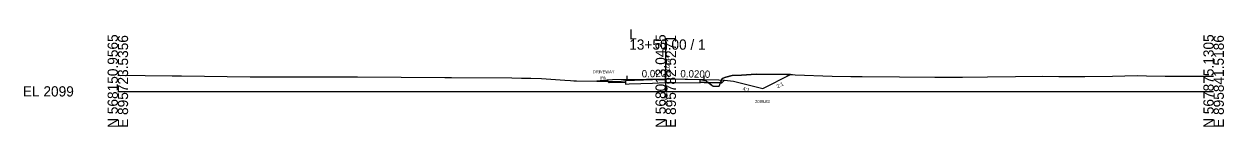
# Model space of a CAD drawing. Extents: x -26 to 1603, y -10 to 13527.
# Drawn here: x -25.7 to 302.8, y 990.3 to 1017 of the extents above; entities that cross this region are included whole.
import ezdxf

# ---------------------------------------------------------------- set-up
doc = ezdxf.new("R2010")
doc.units = 0
for name, color, linetype in [('Default', 7, 'Continuous'), ('Exist XS Center Line Elevation Label', 7, 'Continuous'), ('Exist XS Ground Line', 7, 'Continuous'), ('Old_Level_61', 7, 'Continuous'), ('Old_Level_63', 7, 'Continuous'), ('Prop XS Ditch Slope Text', 7, 'Continuous'), ('Prop XS Ditch Standard Text', 7, 'Continuous'), ('Prop XS Earthwork Shape', 7, 'Continuous'), ('Prop XS EOT Tick Mark', 7, 'Continuous'), ('Prop XS Finish Grade', 7, 'Continuous'), ('Prop XS Finish Grade Earthwork', 7, 'Continuous'), ('Prop XS Finish Grade Paved Shoulder', 7, 'Continuous'), ('Prop XS Finish Grade Pavement', 7, 'Continuous'), ('Prop XS Side Slope Text', 7, 'Continuous'), ('Prop XS Subgrade Earthwork', 7, 'Continuous'), ('Prop XSC Text', 7, 'Continuous')]:
    doc.layers.add(name, color=color, linetype=linetype)

msp = doc.modelspace()

# ---------------------------------------------------------------- linework, layer by layer
at = {"layer": 'Exist XS Ground Line'}
for p, q in [((0, 1004.41), (7.48, 1004.32)), ((7.48, 1004.32), (14.85, 1004.22)), ((14.85, 1004.22), (17.43, 1004.21)), ((17.43, 1004.21), (36.21, 1003.97)), ((36.21, 1003.97), (37.59, 1003.97)), ((37.59, 1003.97), (62.57, 1004)), ((62.57, 1004), (65.6, 1003.99)), ((65.6, 1003.99), (89.54, 1003.82)), ((89.54, 1003.82), (90.36, 1003.82)), ((90.36, 1003.82), (91.39, 1003.81)), ((91.39, 1003.81), (107.89, 1003.73)), ((107.89, 1003.73), (110.48, 1003.66)), ((110.48, 1003.66), (113.06, 1003.59)), ((113.06, 1003.59), (115.98, 1003.52)), ((115.98, 1003.52), (122.4, 1003.04)), ((122.4, 1003.04), (123.92, 1002.94)), ((123.92, 1002.94), (124.85, 1002.88)), ((124.85, 1002.88), (125.58, 1002.88)), ((125.58, 1002.88), (137.27, 1002.72)), ((137.27, 1002.72), (138.97, 1002.98)), ((138.97, 1002.98), (146.39, 1003.25)), ((146.39, 1003.25), (149.78, 1003.4)), ((149.78, 1003.4), (152.57, 1003.41)), ((152.57, 1003.41), (159.47, 1003.25)), ((159.47, 1003.25), (160.35, 1003.11)), ((160.35, 1003.11), (160.94, 1002.96)), ((160.94, 1002.96), (161.38, 1002.64)), ((161.38, 1002.64), (162.98, 1001.42)), ((164.61, 1001.42), (165.41, 1003.49)), ((165.41, 1003.49), (166.46, 1003.85)), ((166.46, 1003.85), (168.2, 1004.31)), ((168.2, 1004.31), (170.75, 1004.48)), ((170.75, 1004.48), (174.75, 1004.74)), ((174.75, 1004.74), (183.06, 1004.63)), ((183.06, 1004.63), (184.72, 1004.6)), ((184.72, 1004.6), (185.45, 1004.57)), ((185.45, 1004.57), (195.54, 1004.2)), ((195.54, 1004.2), (200.72, 1004.05)), ((200.72, 1004.05), (203.8, 1004.09)), ((203.8, 1004.09), (214.04, 1003.99)), ((214.04, 1003.99), (223.63, 1003.92)), ((223.63, 1003.92), (231.22, 1003.89)), ((231.22, 1003.89), (238.12, 1003.99)), ((238.12, 1003.99), (245.78, 1004.09)), ((245.78, 1004.09), (253.18, 1004.17)), ((253.18, 1004.17), (257.58, 1004.08)), ((257.58, 1004.08), (258.88, 1004.08)), ((258.88, 1004.08), (263.3, 1004.08)), ((263.3, 1004.08), (264.77, 1004.09)), ((264.77, 1004.09), (272.31, 1004.19)), ((272.31, 1004.19), (279.05, 1004.31)), ((279.05, 1004.31), (281.65, 1004.25)), ((281.65, 1004.25), (286.77, 1004.18)), ((286.77, 1004.18), (290.47, 1004.19)), ((290.47, 1004.19), (300, 1004.17)), ((162.98, 1001.42), (163.92, 1001.42)), ((163.92, 1001.42), (164.61, 1001.42))]:
    msp.add_line(p, q, dxfattribs=at)
at = {"layer": 'Old_Level_61'}
for p, q in [((138.96, 1002.98), (138.96, 1001.98)), ((139.96, 1002.02), (146.39, 1002.25)), ((146.39, 1002.25), (149.78, 1002.4)), ((149.78, 1002.4), (152.57, 1002.41)), ((152.57, 1002.41), (159.44, 1002.33)), ((159.44, 1002.33), (159.47, 1002.32)), ((159.47, 1002.32), (159.47, 1003.25)), ((138.96, 1001.98), (138.97, 1001.98)), ((138.97, 1001.98), (139.96, 1002.02))]:
    msp.add_line(p, q, dxfattribs=at)
at = {"layer": 'Old_Level_63'}
for p, q in [((150, 1000), (150, 1014.21)), ((0, 1000), (150, 1000)), ((150, 1000), (300, 1000))]:
    msp.add_line(p, q, dxfattribs=at)
at = {"layer": 'Prop XS Earthwork Shape'}
for points in [[(133.95, 1003.03), (131.14, 1002.8), (134.21, 1002.76)], [(133.95, 1003.03), (131.14, 1002.8), (134.21, 1002.76)], [(134.64, 1002.34), (134.21, 1002.76), (137.27, 1002.72), (138.96, 1002.98), (138.96, 1002.43)], [(134.64, 1002.34), (134.21, 1002.76), (137.27, 1002.72), (138.96, 1002.98), (138.96, 1002.43)], [(161.38, 1002.64), (161.67, 1002.41), (160.55, 1002.44), (159.47, 1002.46), (159.47, 1003.25), (160.35, 1003.11), (160.94, 1002.96)], [(161.38, 1002.64), (161.67, 1002.41), (160.55, 1002.44), (159.47, 1002.46), (159.47, 1003.25), (160.35, 1003.11), (160.94, 1002.96)], [(164.61, 1001.42), (164.97, 1002.35), (161.67, 1002.41), (162.98, 1001.42), (163.92, 1001.42)], [(164.61, 1001.42), (164.97, 1002.35), (161.67, 1002.41), (162.98, 1001.42), (163.92, 1001.42)], [(166.05, 1003.03), (168.56, 1002.83), (176.57, 1000.83), (184.14, 1004.61), (183.06, 1004.63), (174.75, 1004.74), (170.75, 1004.48), (168.2, 1004.31), (166.46, 1003.85), (165.41, 1003.49), (164.97, 1002.35), (165.36, 1002.34)], [(166.05, 1003.03), (168.56, 1002.83), (176.57, 1000.83), (184.14, 1004.61), (183.06, 1004.63), (174.75, 1004.74), (170.75, 1004.48), (168.2, 1004.31), (166.46, 1003.85), (165.41, 1003.49), (164.97, 1002.35), (165.36, 1002.34)]]:
    msp.add_lwpolyline(points, close=True, dxfattribs=at)
at = {"layer": 'Prop XS EOT Tick Mark'}
for p, q in [((139.45, 1003.23), (139.45, 1004.23)), ((160.55, 1003.23), (160.55, 1004.23))]:
    msp.add_line(p, q, dxfattribs=at)
at = {"layer": 'Prop XS Finish Grade'}
for p, q in [((135.45, 1003.15), (133.95, 1003.03)), ((164.55, 1003.15), (166.05, 1003.03))]:
    msp.add_line(p, q, dxfattribs=at)
at = {"layer": 'Prop XS Finish Grade Earthwork'}
for p, q in [((133.95, 1003.03), (131.14, 1002.8)), ((166.05, 1003.03), (168.56, 1002.83)), ((168.56, 1002.83), (176.57, 1000.83)), ((176.57, 1000.83), (184.14, 1004.61))]:
    msp.add_line(p, q, dxfattribs=at)
at = {"layer": 'Prop XS Finish Grade Paved Shoulder'}
for p, q in [((139.45, 1003.23), (135.45, 1003.15)), ((160.55, 1003.23), (164.55, 1003.15))]:
    msp.add_line(p, q, dxfattribs=at)
at = {"layer": 'Prop XS Finish Grade Pavement'}
for p, q in [((139.45, 1003.23), (150, 1003.44)), ((150, 1003.44), (160.55, 1003.23))]:
    msp.add_line(p, q, dxfattribs=at)
at = {"layer": 'Prop XS Subgrade Earthwork'}
for p, q in [((134.64, 1002.34), (133.95, 1003.03)), ((138.96, 1002.43), (134.64, 1002.34)), ((138.96, 1002.43), (138.96, 1002.98)), ((159.47, 1002.46), (159.47, 1003.25)), ((160.55, 1002.44), (159.47, 1002.46)), ((160.55, 1002.44), (165.36, 1002.34)), ((165.36, 1002.34), (166.05, 1003.03))]:
    msp.add_line(p, q, dxfattribs=at)

# ---------------------------------------------------------------- texts
at = {"layer": 'Default'}
for rotation, p in [(1.1458, (143.44, 1003.81)), (358.8542, (153.99, 1003.86))]:
    msp.add_text('0.0200', height=2, rotation=rotation, dxfattribs=at).set_placement(p)
at = {"layer": 'Exist XS Center Line Elevation Label'}
msp.add_text('2102.41', height=1, rotation=90, dxfattribs=at).set_placement((150.5, 996.16))
at = {"layer": 'Old_Level_63'}
for s, p in [('N 568150.9565', (0, 990)), ('E 895723.5356', (2.8, 990)), ('N 568013.0435', (150, 990)), ('E 895782.5271', (152.8, 990)), ('N 567875.1305', (300, 990)), ('E 895841.5186', (302.8, 990))]:
    msp.add_text(s, height=2.8, rotation=90, dxfattribs=at).set_placement(p)
for s, p in [('L', (140, 1014.21)), ('13+50.00 / 1', (140, 1011.41)), ('EL 2099', (-26, 998.6))]:
    msp.add_text(s, height=2.8, dxfattribs=at).set_placement(p)
at = {"layer": 'Prop XS Ditch Slope Text'}
msp.add_text('4:1', height=1, rotation=345.9767, dxfattribs=at).set_placement((170.95, 1000.32))
at = {"layer": 'Prop XS Ditch Standard Text'}
for s, p in [('DRIVEWAY', (130.07, 1004.98)), ('2099.83', (174.48, 996.83))]:
    msp.add_text(s, height=0.8, dxfattribs=at).set_placement(p)
msp.add_text('8%', height=0.8, rotation=4.5687, dxfattribs=at).set_placement((132.02, 1003.26))
at = {"layer": 'Prop XS Side Slope Text'}
msp.add_text('2:1', height=1, rotation=26.5431, dxfattribs=at).set_placement((180.64, 1000.85))
at = {"layer": 'Prop XSC Text'}
msp.add_text(' 2102.44', height=1.2, rotation=90, dxfattribs=at).set_placement((151.2, 1003.44))

doc.saveas('drawing.dxf')
